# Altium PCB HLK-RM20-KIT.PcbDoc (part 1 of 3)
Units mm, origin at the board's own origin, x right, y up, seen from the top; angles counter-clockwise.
Board outline 152 x 109 mm, 2 copper layers (Top Layer, Bottom Layer), stack 0.325 mm thick; 212 components, 285 nets, 988 pads, 747 vias.
Unrouted connection lines stored in the file: 195.
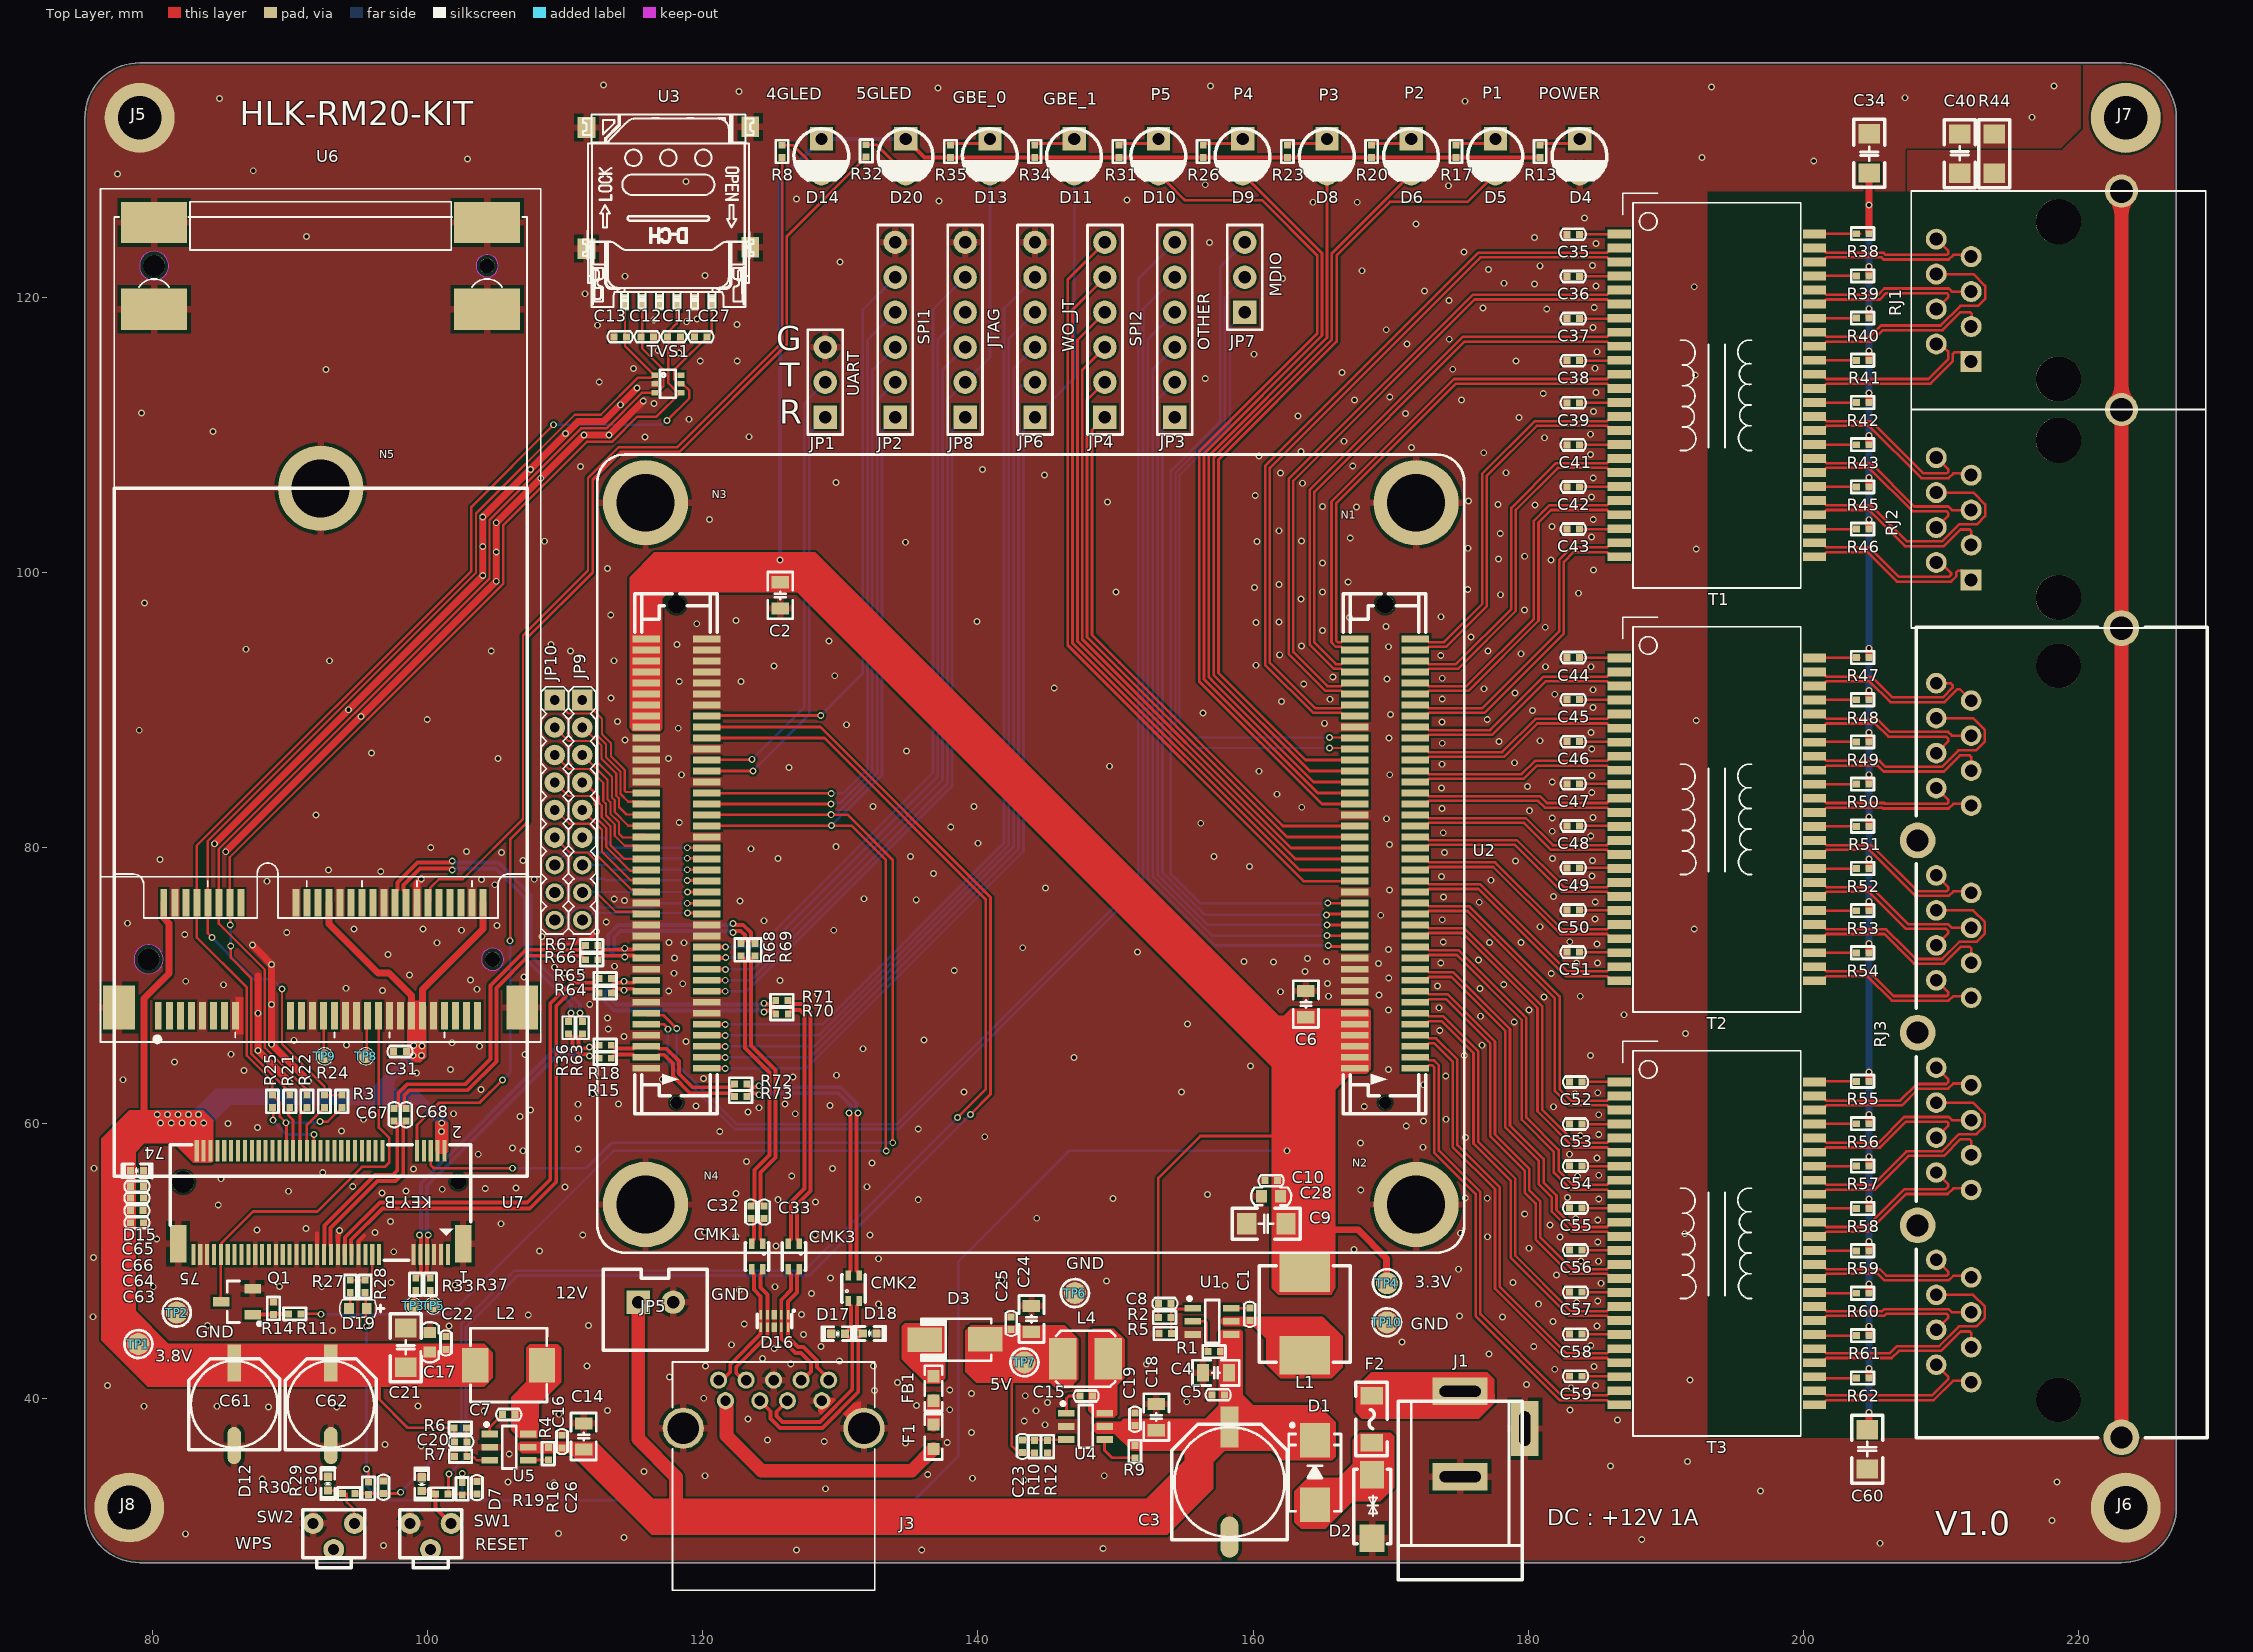
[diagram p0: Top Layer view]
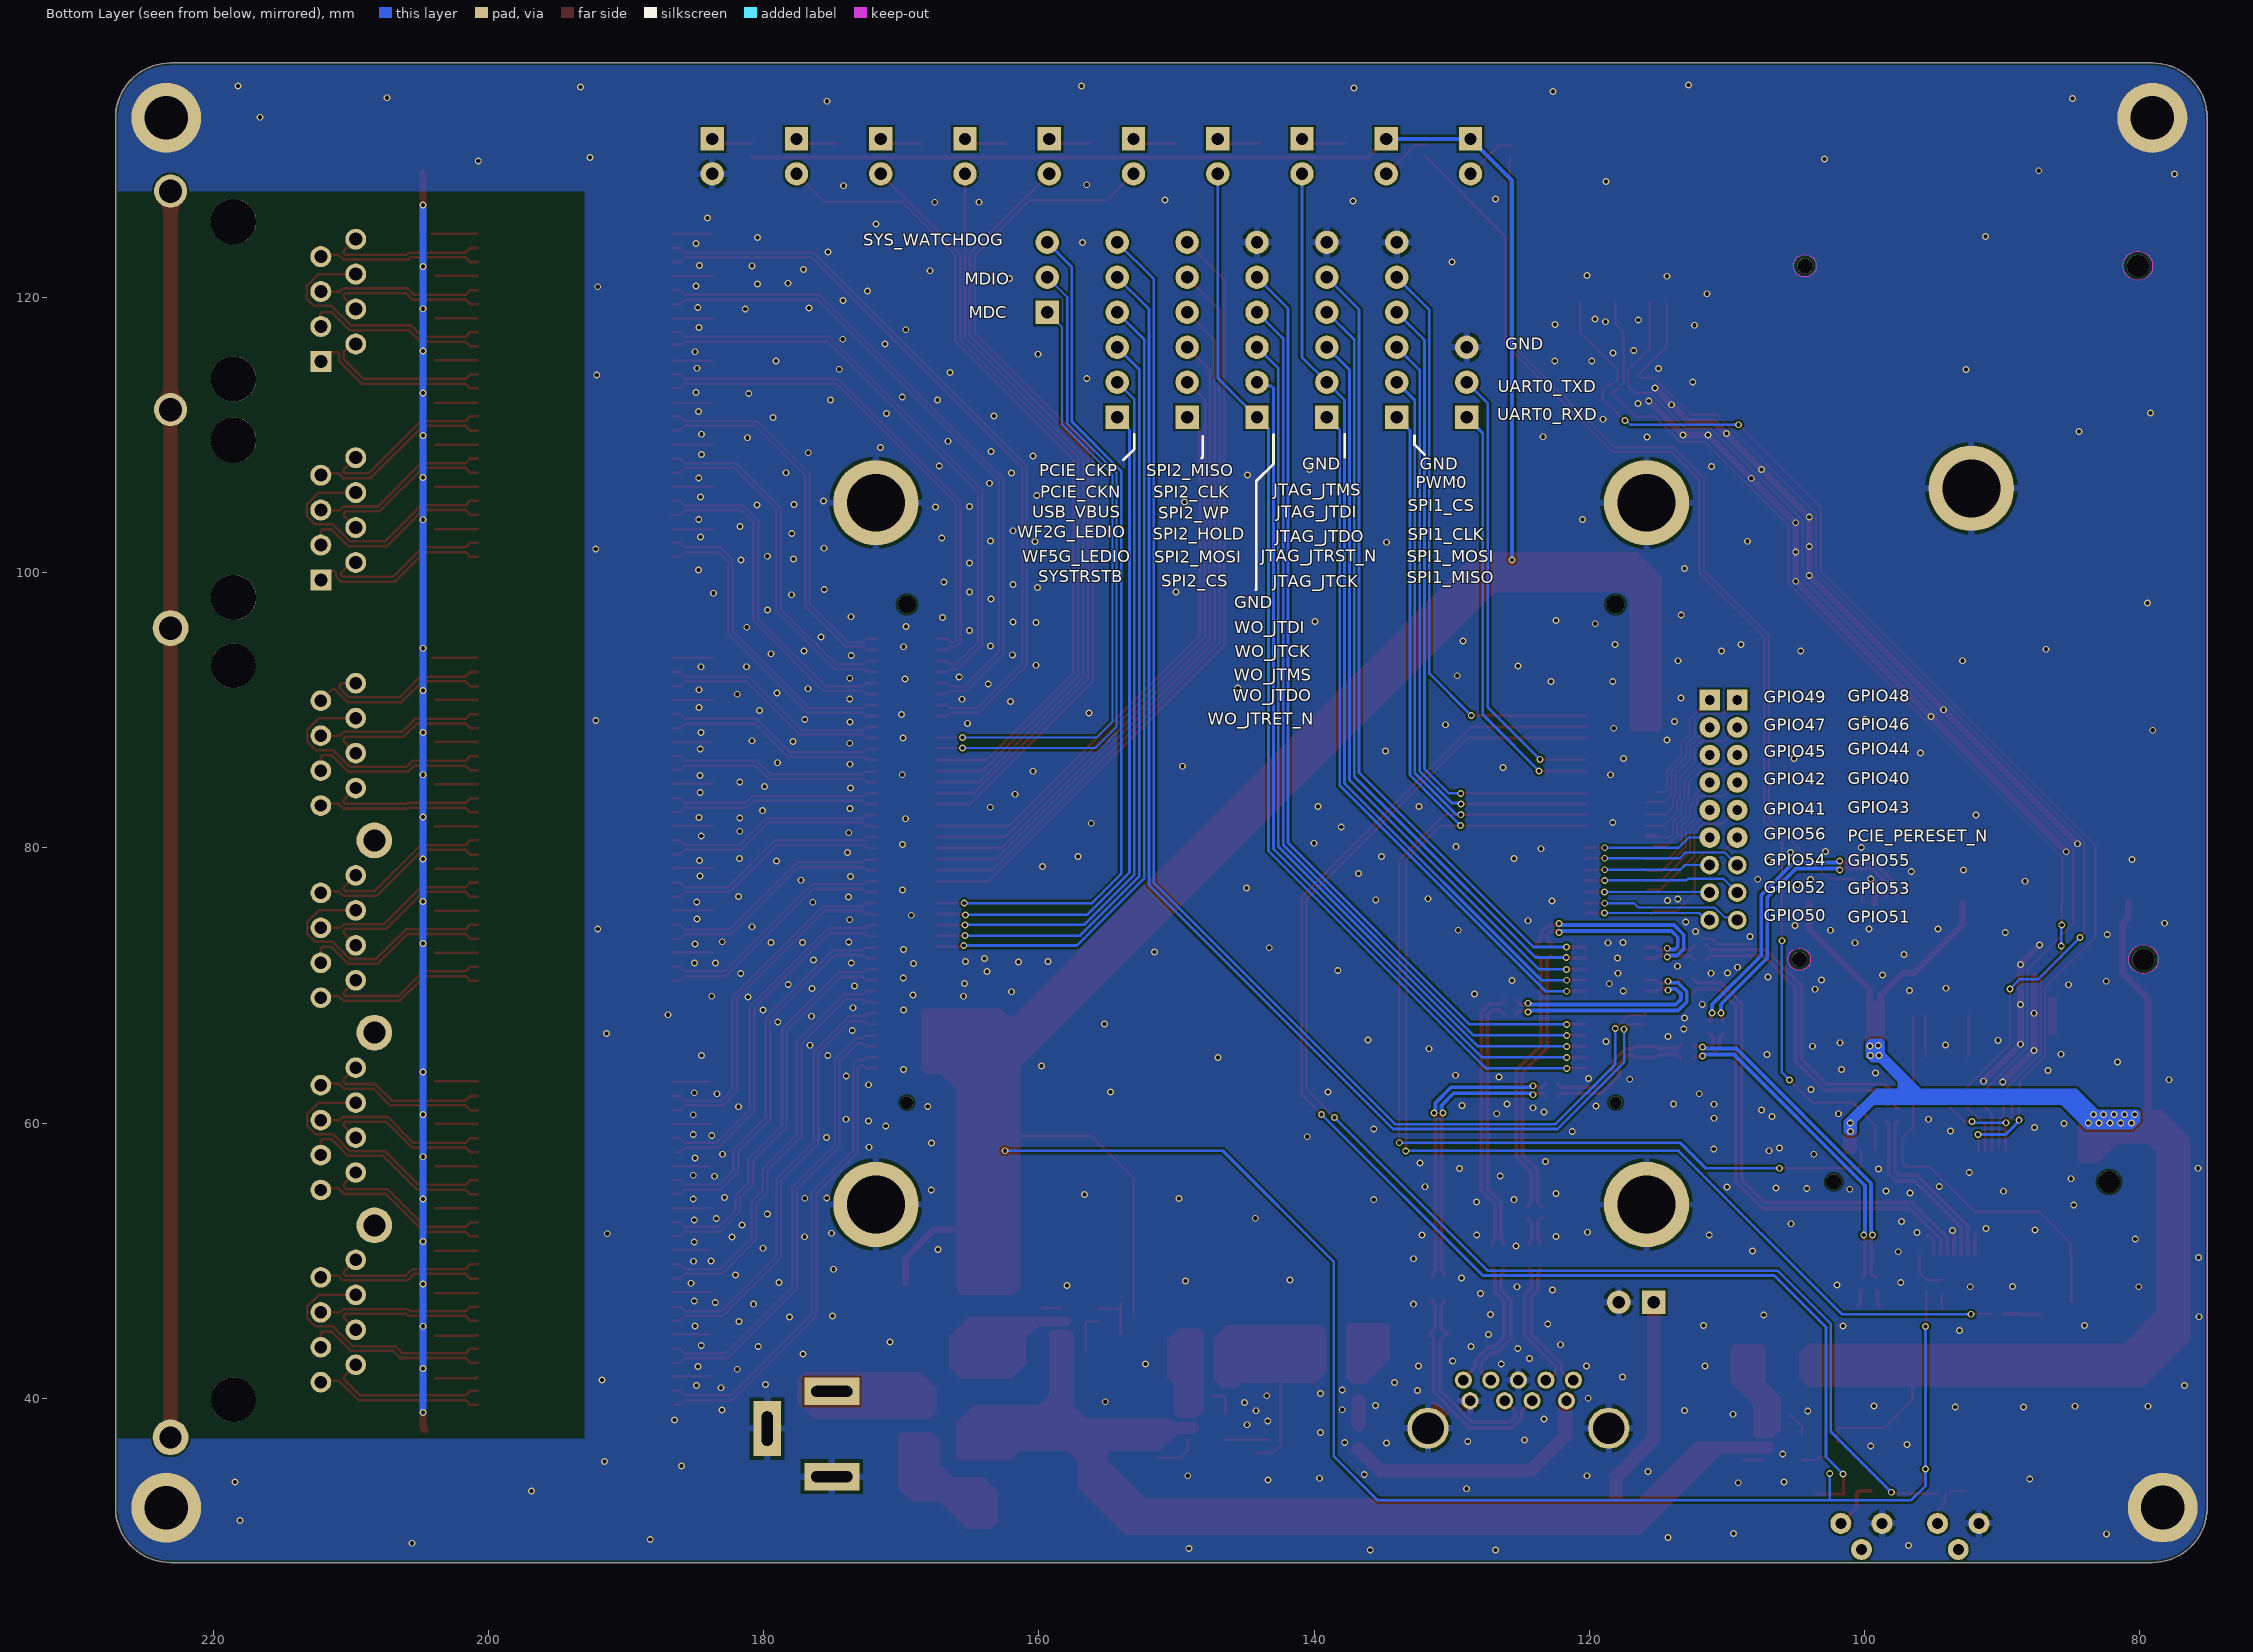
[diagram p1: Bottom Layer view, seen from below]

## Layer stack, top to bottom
Top Solder: solder mask 0.0102, Solder Resist, Dk 3.5
Top Layer: signal copper 0.0356
Dielectric1: core 0.254, FR-4, Dk 4.2
Bottom Layer: signal copper 0.0356
Bottom Solder: solder mask 0.0102, Solder Resist, Dk 3.5

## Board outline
75.089,32.059 75.089,133.053 cw(c79.089,133.053) 79.089,137.053 223.092,137.053 223.092,137.048 cw(c223.092,133.048) 227.092,133.048 227.093,133.047 227.093,32.053 cw(c223.093,32.053) 223.093,28.053 79.095,28.053 79.09,28.058 cw(c79.09,32.058)

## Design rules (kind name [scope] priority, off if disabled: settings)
Clearance [All] p1: gap=0.152 ignorepadtopadclearanceinfootprint=FALSE
DiffPairsRouting 90OHM [InNetClass('90OHM')] p1: maxlimit=0.152 minlimit=0.152 mostfreqgap=0.152 toplayer_minwidth=0.283 toplayer_maxwidth=0.283 toplayer_prefwidth=0.283 bottomlayer_minwidth=0.283 bottomlayer_maxwidth=0.283 bottomlayer_prefwidth=0.283 maxuncoupledlength=12.7
DiffPairsRouting 100OHM [InNetClass('100OHM')] p2: maxlimit=0.152 minlimit=0.152 mostfreqgap=0.152 toplayer_minwidth=0.188 toplayer_maxwidth=0.188 toplayer_prefwidth=0.188 bottomlayer_minwidth=0.188 bottomlayer_maxwidth=0.188 bottomlayer_prefwidth=0.188 maxuncoupledlength=12.7
FabricationTestPointUsage TestPointUsage [All] p1: valid=0 allowmultiple=FALSE
FabricationTestpoint Testpoint [All] p1: side=3 testpointundercomponent=TRUE minsize=1.016 maxsize=2.54 preferedsize=1.524 minholesize=0 maxholesize=1.016 preferedholesize=0.813 testpointgrid=0.025 allowsidetop=TRUE allowsidebottom=TRUE usegrid=TRUE gridtolerance=0
HoleSize [All] p1: absolutevalues=TRUE maxlimit=5 minlimit=0.2 maxpercent=80.000 minpercent=20.000
MatchedLengths DiffPair_USB2.0_5GMatchedLengths [InDifferentialPair ('USB_5G')] p1: tolerance=10 checknetsindiffpair=TRUE checkdiffpairvsdiffpair=FALSE checkxsignals=FALSE checkothers=FALSE
MatchedLengths DiffPair_USB2.0_7621MatchedLengths [InDifferentialPair ('USB')] p2: tolerance=10 checknetsindiffpair=TRUE checkdiffpairvsdiffpair=FALSE checkxsignals=FALSE checkothers=FALSE
MatchedLengths DiffPair_USB3.0TXMatchedLengths [InDifferentialPair ('SSUSB_TX')] p3: tolerance=0.7 checknetsindiffpair=TRUE checkdiffpairvsdiffpair=FALSE checkxsignals=FALSE checkothers=FALSE
MatchedLengths DiffPair_USB3.0RXMatchedLengths [InDifferentialPair ('SSUSB_RX')] p4: tolerance=0.7 checknetsindiffpair=TRUE checkdiffpairvsdiffpair=FALSE checkxsignals=FALSE checkothers=FALSE
MatchedLengths DiffPair_USB2.0_7621MatchedLengths_1 [InDifferentialPair ('USB')] p5: tolerance=5 checknetsindiffpair=TRUE checkdiffpairvsdiffpair=FALSE checkxsignals=FALSE checkothers=FALSE
MatchedLengths DiffPair_USB2.0_5GMatchedLengths_1 [InDifferentialPair ('USB_5G')] p6: tolerance=1 checknetsindiffpair=TRUE checkdiffpairvsdiffpair=FALSE checkxsignals=FALSE checkothers=FALSE
MatchedLengths DiffPair_USB3.0TXMatchedLengths_1 [InDifferentialPair ('SSUSB_TX')] p7: tolerance=0.7 checknetsindiffpair=TRUE checkdiffpairvsdiffpair=FALSE checkxsignals=FALSE checkothers=FALSE
MatchedLengths DiffPair_USB3.0RXMatchedLengths_1 [InDifferentialPair ('SSUSB_RX')] p8: tolerance=0.7 checknetsindiffpair=TRUE checkdiffpairvsdiffpair=FALSE checkxsignals=FALSE checkothers=FALSE
MatchedLengths DiffPair_PCIE_TXMatchedLengths [InDifferentialPair ('PCIE_TX')] p9: tolerance=0.7 checknetsindiffpair=TRUE checkdiffpairvsdiffpair=FALSE checkxsignals=FALSE checkothers=FALSE
MatchedLengths DiffPair_PCIE_CLKMatchedLengths [InDifferentialPair ('PCIE_CLK')] p10: tolerance=0.7 checknetsindiffpair=TRUE checkdiffpairvsdiffpair=FALSE checkxsignals=FALSE checkothers=FALSE
MatchedLengths DiffPair_PCIE_RXMatchedLengths [InDifferentialPair ('PCIE_RX')] p11: tolerance=0.7 checknetsindiffpair=TRUE checkdiffpairvsdiffpair=FALSE checkxsignals=FALSE checkothers=FALSE
MatchedLengths DiffPair_PCIE_RXMatchedLengths_1 [InDifferentialPair ('PCIE_RX')] p12: tolerance=25.4 checknetsindiffpair=TRUE checkdiffpairvsdiffpair=FALSE checkxsignals=FALSE checkothers=FALSE
MatchedLengths [InDifferentialPair ('PCIE_TX')] p13: tolerance=25.4 checknetsindiffpair=TRUE checkdiffpairvsdiffpair=FALSE checkxsignals=FALSE checkothers=FALSE
MatchedLengths DiffPair_PCIE_TXMatchedLengths_1 [InDifferentialPair ('PCIE_TX')] p14: tolerance=0.7 checknetsindiffpair=TRUE checkdiffpairvsdiffpair=FALSE checkxsignals=FALSE checkothers=FALSE
MatchedLengths DiffPair_1MatchedLengths [InDifferentialPair ('PCIE_TX')] p15: tolerance=0.7 checknetsindiffpair=TRUE checkdiffpairvsdiffpair=FALSE checkxsignals=FALSE checkothers=FALSE
PolygonConnect 部分焊盘十字 [All vs HasPad ('U7-76') Or HasPad ('U7-77')Or HasPad ('j4-1')Or HasPad ('j4-2')Or HasPad ('j4-3')Or HasPad ('j4-4')  Or HasPad ('U7-0')        Or HasPad ('U3-0') Or HasPad ('U6-55')Or HasPad ('U6-56') Or HasPad ('U6-63') Or HasPad ('U6-64') Or HasPad ('U6-65') Or HasPad ('U6-66')  Or HasPad ('U2-0')] p1: connectstyle=Relief reliefconductorwidth=0.5 reliefentries=4 polygonreliefangle="90 Angle" airgapwidth=0.254
PolygonConnect M3 [All vs HasFootprint('M3 125X200')] p2: connectstyle=Direct reliefconductorwidth=0.254 reliefentries=4 polygonreliefangle="90 Angle" airgapwidth=0.254
PolygonConnect 全连 [InComponent('D16') or  InComponent('u6')or  InComponent('u1') or  InComponent('u2')  or  InComponent('u3') or  InComponent('u4')or  InComponent('tvs1')          or  InComponent('u7')] p3: connectstyle=Direct reliefconductorwidth=0.254 reliefentries=4 polygonreliefangle="90 Angle" airgapwidth=0.254
PolygonConnect 焊盘全连通孔十字 [(HasFootprint('NANO-SIM_SMN-327') OR HasFootprint('HLK-RM20') OR HasFootprint('C 1206_L') OR HasFootprint('R 1206_L')OR HasFootprint('TEST 1.6')  )] p4: thpad.connectstyle=Relief thpad.reliefconductorwidth=0.5 thpad.reliefentries=4 thpad.polygonreliefangle="90 Angle" thpad.airgapwidth=0.254 smdpad.connectstyle=Direct smdpad.reliefconductorwidth=0.254 smdpad.reliefentries=4 smdpad.polygonreliefangle="90 Angle" smdpad.airgapwidth=0.254 via.connectstyle=Direct via.reliefconductorwidth=0.254 via.reliefentries=4 via.polygonreliefangle="90 Angle" via.airgapwidth=0.254
PolygonConnect [All] p5: thpad.connectstyle=Relief thpad.reliefconductorwidth=0.5 thpad.reliefentries=4 thpad.polygonreliefangle="90 Angle" thpad.airgapwidth=0.254 smdpad.connectstyle=Relief smdpad.reliefconductorwidth=0.5 smdpad.reliefentries=4 smdpad.polygonreliefangle="90 Angle" smdpad.airgapwidth=0.254 via.connectstyle=Direct via.reliefconductorwidth=0.254 via.reliefentries=4 via.polygonreliefangle="90 Angle" via.airgapwidth=0.254
RoutingVias [All] p1: holewidth=0.4 width=0.4 viastyle="Through Hole" minholewidth=0.2 minwidth=0.4 maxholewidth=0.6 maxwidth=0.8
SilkToSilkClearance [All] p1: silktosilkclearance=0
SolderMaskExpansion [All] p1: expansion=0.102 istentingtop=FALSE
Width Width_90ohm [InNetClass('90ohm')] p1 off: maxlimit=0.283 minlimit=0.283 preferedwidth=0.283 minimp=50.000000 maximp=50.000000 favimp=50.000000
Width Width_100ohm [InNetClass('100ohm')] p2 off: maxlimit=0.188 minlimit=0.188 preferedwidth=0.188
Width [All] p3: maxlimit=5 minlimit=0.152 preferedwidth=0.152
25 further rules are at their usual default settings.

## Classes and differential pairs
component class HLK-RM20-KIT-5G: C61 C62 C63 C64 C65 C66 C67 C68 D15 D19 D20 R21 R22 R24 R25 R27 R28 R32 R33 R37 R64 R65 R66 R67 TP3 TP5 U7
component class HLK-RM20-KIT-4G: 1 2 C7 C11 C12 C13 C14 C16 C17 C20 C21 C22 C27 C31 D14 L2 Q1 R3 R4 R6 R7 R8 R11 R14 R15 R18 R36 R63 TP1 TP2 TP8 TP9 TVS1 U3 U5 U6
net class 90OHM: 4GUSB_D1_N 4GUSB_D1_P 4GUSB_D_N 4GUSB_D_P 5G_SSUSB_RX_N 5G_SSUSB_RX_P 5G_USB_TX_N 5G_USB_TX_P DZSS_RX_N DZSS_RX_P DZSS_TX_N DZSS_TX_P DZUSB_D_N DZUSB_D_P NetCMK1_3 NetCMK1_4 NetCMK2_1 NetCMK2_2 NetCMK3_3 NetCMK3_4 SS_RX_N SS_RX_P SS_TX_N SS_TX_P USB_D_N USB_D_P
net class 100OHM: ESW_A_P1_TXV_N ESW_A_P1_TXV_P ESW_A_P2_TXV_N ESW_A_P2_TXV_P ESW_A_P3_TXV_N ESW_A_P3_TXV_P ESW_A_P4_TXV_N ESW_A_P4_TXV_P ESW_A_P5_TXV_N ESW_A_P5_TXV_P ESW_B_P1_TXV_N ESW_B_P1_TXV_P ESW_B_P2_TXV_N ESW_B_P2_TXV_P ESW_B_P3_TXV_N ESW_B_P3_TXV_P ESW_B_P4_TXV_N ESW_B_P4_TXV_P ESW_B_P5_TXV_N ESW_B_P5_TXV_P ESW_C_P1_TXV_N ESW_C_P1_TXV_P ESW_C_P2_TXV_N ESW_C_P2_TXV_P ESW_C_P3_TXV_N ESW_C_P3_TXV_P ESW_C_P4_TXV_N ESW_C_P4_TXV_P ESW_C_P5_TXV_N ESW_C_P5_TXV_P ESW_D_P1_TXV_N ESW_D_P1_TXV_P ESW_D_P2_TXV_N ESW_D_P2_TXV_P ESW_D_P3_TXV_N ESW_D_P3_TXV_P ESW_D_P4_TXV_N ESW_D_P4_TXV_P ESW_D_P5_TXV_N ESW_D_P5_TXV_P MTXV_P0_A_N MTXV_P0_A_P MTXV_P0_B_N MTXV_P0_B_P MTXV_P0_C_N MTXV_P0_C_P MTXV_P0_D_N MTXV_P0_D_P MTXV_P1_A_N MTXV_P1_A_P MTXV_P1_B_N MTXV_P1_B_P MTXV_P1_C_N MTXV_P1_C_P MTXV_P1_D_N MTXV_P1_D_P MTXV_P2_A_N MTXV_P2_A_P MTXV_P2_B_N MTXV_P2_B_P MTXV_P2_C_N MTXV_P2_C_P MTXV_P2_D_N MTXV_P2_D_P MTXV_P3_A_N MTXV_P3_A_P MTXV_P3_B_N MTXV_P3_B_P MTXV_P3_C_N MTXV_P3_C_P MTXV_P3_D_N MTXV_P3_D_P MTXV_P4_A_N MTXV_P4_A_P MTXV_P4_B_N MTXV_P4_B_P MTXV_P4_C_N MTXV_P4_C_P MTXV_P4_D_N MTXV_P4_D_P MTXV_P5_A_N MTXV_P5_A_P MTXV_P5_B_N MTXV_P5_B_P MTXV_P5_C_N MTXV_P5_C_P MTXV_P5_D_N MTXV_P5_D_P P0_A_TXV_N P0_A_TXV_P P0_B_TXV_N P0_B_TXV_P P0_C_TXV_N P0_C_TXV_P P0_D_TXV_N P0_D_TXV_P
component class HLK-RM20-KIT-POWER_LED: 56 C1 C2 C3 C4 C5 C6 C8 C9 C10 C15 C18 C19 C23 C24 C25 C26 C28 C30 C32 C33 CMK1 CMK2 CMK3 D1 D2 D3 D4 D5 D6 D7 D8 D9 D10 D11 D12 D13 D16 D17 D18 F1 F2 FB1 J1 J3 J5 J6 J7 J8 JP1 JP2 JP3 JP4 JP5 JP6 JP7 JP8 JP9 JP10 L1 L4 m R1 R2 R5 R9 R10 R12 R13 R16 R17 R19 R20 R23 R26 R29 R30 R31 R34 R35 R68 R69 R70 R71 R72 R73 SW1 SW2 TP4 TP6 TP7 TP10 U1 U2 U4
component class HLK-RM20-KIT-RJ45: C34 C35 C36 C37 C38 C39 C40 C41 C42 C43 C44 C45 C46 C47 C48 C49 C50 C51 C52 C53 C54 C55 C56 C57 C58 C59 C60 R38 R39 R40 R41 R42 R43 R44 R45 R46 R47 R48 R49 R50 R51 R52 R53 R54 R55 R56 R57 R58 R59 R60 R61 R62 RJ1 RJ2 RJ3 T1 T2 T3
differential pair 4GUSB_D1: +4GUSB_D1_P -4GUSB_D1_N
differential pair USB_D: +USB_D_P -USB_D_N
differential pair DZUSB_D: +DZUSB_D_P -DZUSB_D_N
differential pair DZSS_TX: +DZSS_TX_P -DZSS_TX_N
differential pair DZSS_RX: +DZSS_RX_P -DZSS_RX_N
differential pair 4GUSB_D: +4GUSB_D_P -4GUSB_D_N
differential pair 5G_USB_TX: +5G_USB_TX_P -5G_USB_TX_N
differential pair 5G_SSUSB_TX: +5G_SSUSB_TX_P -5G_SSUSB_TX_N
differential pair 5G_SSUSB_RX: +5G_SSUSB_RX_P -5G_SSUSB_RX_N
differential pair MTXV_P5_D: +MTXV_P5_D_P -MTXV_P5_D_N
differential pair MTXV_P5_C: +MTXV_P5_C_P -MTXV_P5_C_N
differential pair MTXV_P5_B: +MTXV_P5_B_P -MTXV_P5_B_N
differential pair MTXV_P5_A: +MTXV_P5_A_P -MTXV_P5_A_N
differential pair MTXV_P4_D: +MTXV_P4_D_P -MTXV_P4_D_N
differential pair MTXV_P4_C: +MTXV_P4_C_P -MTXV_P4_C_N
differential pair MTXV_P4_B: +MTXV_P4_B_P -MTXV_P4_B_N
differential pair MTXV_P4_A: +MTXV_P4_A_P -MTXV_P4_A_N
differential pair MTXV_P3_D: +MTXV_P3_D_P -MTXV_P3_D_N
differential pair MTXV_P3_C: +MTXV_P3_C_P -MTXV_P3_C_N
differential pair MTXV_P3_B: +MTXV_P3_B_P -MTXV_P3_B_N
differential pair MTXV_P3_A: +MTXV_P3_A_P -MTXV_P3_A_N
differential pair MTXV_P2_D: +MTXV_P2_D_P -MTXV_P2_D_N
differential pair MTXV_P2_C: +MTXV_P2_C_P -MTXV_P2_C_N
differential pair MTXV_P2_B: +MTXV_P2_B_P -MTXV_P2_B_N
differential pair MTXV_P2_A: +MTXV_P2_A_P -MTXV_P2_A_N
differential pair MTXV_P1_D: +MTXV_P1_D_P -MTXV_P1_D_N
differential pair MTXV_P1_C: +MTXV_P1_C_P -MTXV_P1_C_N
differential pair MTXV_P1_B: +MTXV_P1_B_P -MTXV_P1_B_N
differential pair MTXV_P1_A: +MTXV_P1_A_P -MTXV_P1_A_N
differential pair MTXV_P0_D: +MTXV_P0_D_P -MTXV_P0_D_N
differential pair MTXV_P0_C: +MTXV_P0_C_P -MTXV_P0_C_N
differential pair MTXV_P0_B: +MTXV_P0_B_P -MTXV_P0_B_N
differential pair MTXV_P0_A: +MTXV_P0_A_P -MTXV_P0_A_N
differential pair P0_D_TXV: +P0_D_TXV_P -P0_D_TXV_N
differential pair P0_C_TXV: +P0_C_TXV_P -P0_C_TXV_N
differential pair P0_B_TXV: +P0_B_TXV_P -P0_B_TXV_N
differential pair P0_A_TXV: +P0_A_TXV_P -P0_A_TXV_N
differential pair ESW_D_P5_TXV: +ESW_D_P5_TXV_P -ESW_D_P5_TXV_N
differential pair ESW_D_P4_TXV: +ESW_D_P4_TXV_P -ESW_D_P4_TXV_N
differential pair ESW_D_P3_TXV: +ESW_D_P3_TXV_P -ESW_D_P3_TXV_N
differential pair ESW_D_P2_TXV: +ESW_D_P2_TXV_P -ESW_D_P2_TXV_N
differential pair ESW_D_P1_TXV: +ESW_D_P1_TXV_P -ESW_D_P1_TXV_N
differential pair ESW_C_P5_TXV: +ESW_C_P5_TXV_P -ESW_C_P5_TXV_N
differential pair ESW_C_P4_TXV: +ESW_C_P4_TXV_P -ESW_C_P4_TXV_N
differential pair ESW_C_P3_TXV: +ESW_C_P3_TXV_P -ESW_C_P3_TXV_N
differential pair ESW_C_P2_TXV: +ESW_C_P2_TXV_P -ESW_C_P2_TXV_N
differential pair ESW_C_P1_TXV: +ESW_C_P1_TXV_P -ESW_C_P1_TXV_N
differential pair ESW_B_P5_TXV: +ESW_B_P5_TXV_P -ESW_B_P5_TXV_N
differential pair ESW_B_P4_TXV: +ESW_B_P4_TXV_P -ESW_B_P4_TXV_N
differential pair ESW_B_P3_TXV: +ESW_B_P3_TXV_P -ESW_B_P3_TXV_N
differential pair ESW_B_P2_TXV: +ESW_B_P2_TXV_P -ESW_B_P2_TXV_N
differential pair ESW_B_P1_TXV: +ESW_B_P1_TXV_P -ESW_B_P1_TXV_N
differential pair ESW_A_P5_TXV: +ESW_A_P5_TXV_P -ESW_A_P5_TXV_N
differential pair ESW_A_P4_TXV: +ESW_A_P4_TXV_P -ESW_A_P4_TXV_N
differential pair ESW_A_P3_TXV: +ESW_A_P3_TXV_P -ESW_A_P3_TXV_N
differential pair ESW_A_P2_TXV: +ESW_A_P2_TXV_P -ESW_A_P2_TXV_N
differential pair ESW_A_P1_TXV: +ESW_A_P1_TXV_P -ESW_A_P1_TXV_N
differential pair SS_TX: +SS_TX_P -SS_TX_N
differential pair SS_RX: +SS_RX_P -SS_RX_N

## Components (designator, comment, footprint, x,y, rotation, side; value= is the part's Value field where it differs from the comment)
C1 "100nF" "C 0402_L" 159.751,46.1 r270 top
C2 "22uF" "C 0805_L" 125.628,98.349 r90 top value=100pF
C3 "220uF" "CT 8*12 - C" 158.283,33.908 r90 top
C4 "10uF" "C 0805_L" 157.293,41.85 r0 top value=100pF
C5 "100nF" "C 0402_L" 157.457,40.25 r180 top
C6 "22uF" "C 0805_L" 163.83,68.646 r270 top value=100pF
C7 "100nF" "C 0402_L" 105.9,38.816 r0 top
C8 "100pF" "C 0402_L" 153.586,46.888 r180 top
C9 "47uF" "C 1206_L" 160.937,52.69 r0 top
C10 "100nF" "C 0402_L" 161.306,55.813 r180 top
C11 "33pF" "C 0402_L" 117.909,117.145 r0 top
C12 "33pF" "C 0402_L" 115.952,117.145 r0 top
C13 "33pF" "C 0402_L" 113.995,117.145 r180 top
C14 "10uF" "C 0805_L" 111.341,37.221 r270 top value=100pF
C15 "100nF" "C 0402_L" 147.857,40.17 r0 top
C16 "100nF" "C 0402_L" 109.766,36.855 r90 top
C17 "10uF" "C 0603_L" 100.165,44.08 r90 top
C18 "10uF" "C 0805_L" 152.956,38.63 r270 top value=100pF
C19 "100nF" "C 0402_L" 151.403,38.474 r90 top
C20 "100pF" "C 0402_L" 102.415,36.836 r180 top
C21 "47uF" "C 1206_l" 98.412,43.71 r270 top
C22 "100nF" "C 0402_L" 101.333,44.018 r90 top
C23 "47pF" "C 0402_L" 143.23,36.504 r270 top value=100pF
C24 "22uF" "C 0805_L" 143.884,45.761 r270 top value=100pF
C25 "100nF" "C 0402_L" 142.411,45.441 r90 top
C26 "100nF" "C 0402_L" 103.582,33.503 r270 top
C27 "100nF" "C 0402_L" 119.865,117.145 r0 top
C28 "10uF" "C 0603_L" 161.301,54.675 r180 top
C30 "100nF" "C 0402_L" 96.794,33.534 r270 top
C31 "100nF" "C 0402_L" 97.994,65.199 r180 top
C32 "0.1uF" "C 0402_L" 123.501,53.529 r90 top
C33 "0.1uF" "C 0402_L" 124.458,53.529 r90 top
C34 "1000pF,2KV,SMD,1206" "C 1206_L" 204.772,130.444 r90 top
C35 "0.1uF" "C 0402_L" 183.259,124.588 r0 top
C36 "0.1uF" "C 0402_L" 183.259,121.528 r0 top
C37 "0.1uF" "C 0402_L" 183.259,118.468 r0 top
C38 "0.1uF" "C 0402_L" 183.259,115.408 r0 top
C39 "0.1uF" "C 0402_L" 183.259,112.348 r0 top
C40 "1000pF/2KV" "C 1206_L" 211.34,130.478 r270 top
C41 "0.1uF" "C 0402_L" 183.259,109.288 r0 top
C42 "0.1uF" "C 0402_L" 183.259,106.229 r0 top
C43 "0.1uF" "C 0402_L" 183.259,103.169 r0 top
C44 "0.1uF" "C 0402_L" 183.259,93.831 r0 top
C45 "0.1uF" "C 0402_L" 183.259,90.773 r0 top
C46 "0.1uF" "C 0402_L" 183.259,87.715 r0 top
C47 "0.1uF" "C 0402_L" 183.259,84.656 r0 top
C48 "0.1uF" "C 0402_L" 183.259,81.598 r0 top
C49 "0.1uF" "C 0402_L" 183.259,78.54 r0 top
C50 "0.1uF" "C 0402_L" 183.259,75.481 r0 top
C51 "0.1uF" "C 0402_L" 183.259,72.423 r0 top
C52 "0.1uF" "C 0402_L" 183.428,62.987 r0 top
C53 "0.1uF" "C 0402_L" 183.428,59.931 r0 top
C54 "0.1uF" "C 0402_L" 183.428,56.876 r0 top
C55 "0.1uF" "C 0402_L" 183.428,53.821 r0 top
C56 "0.1uF" "C 0402_L" 183.428,50.766 r0 top
C57 "0.1uF" "C 0402_L" 183.428,47.711 r0 top
C58 "0.1uF" "C 0402_L" 183.428,44.656 r0 top
C59 "0.1uF" "C 0402_L" 183.428,41.601 r0 top
C60 "1000pF,2KV,SMD,1206" "C 1206_L" 204.62,36.312 r270 top
C61 "220uF" "CT 6*6 - R" 85.941,39.562 r90 top
C62 "220uF" "CT 6*6 - R" 92.97,39.562 r90 top
C63 "1uF" "C 0402_L" 78.879,52.756 r0 top
C64 "100nF" "C 0402_L" 78.874,53.631 r0 top
C65 "33pF" "C 0402_L" 78.879,55.397 r0 top
C66 "10pF" "C 0402_L" 78.879,54.559 r0 top
C67 "0.1uF" "C 0402_L" 97.574,60.604 r270 top
C68 "0.1uF" "C 0402_L" 98.447,60.607 r270 top
CMK1 "ACM2012E-2P" SMD_4P 123.941,50.303 r270 top
CMK2 "ACM2012E-2P" SMD_4P 130.962,47.992 r90 top
CMK3 "ACM2012E-2P" SMD_4P 126.619,50.303 r270 top
D1 "SS34" SMB 164.487,34.598 r90 top
D2 "SMAJ26CA" DO-214AC 168.641,29.827 r90 top
D3 "SS12" SMA 138.322,44.272 r180 top
D4 "RED" "LED 3MM-R" 183.729,130.251 r270 top
D5 "YELLOW" "LED 3MM-Y" 177.606,130.251 r270 top
D6 "YELLOW" "LED 3MM-Y" 171.484,130.251 r270 top
D7 "BPESD0402-05ST" esd0402 99.569,33.759 r270 top
D8 "YELLOW" "LED 3MM-Y" 165.361,130.251 r270 top
D9 "YELLOW" "LED 3MM-Y" 159.238,130.251 r270 top
D10 "YELLOW" "LED 3MM-Y" 153.116,130.251 r270 top
D11 "YELLOW" "LED 3MM-Y" 146.993,130.251 r270 top
D12 "BPESD0402-05ST" esd0402 92.755,33.789 r270 top
D13 "YELLOW" "LED 3MM-Y" 140.871,130.251 r270 top
D14 "RED" "LED 3MM-G" 128.626,130.251 r270 top
D15 "ESDA-05N" ESD0402#1 78.888,57.54 r180 top
D16 "B0524P" DFN-10 125.203,45.613 r180 top
D17 "BPESD0402-05ST" ESD0402#2 129.826,44.695 r0 top
D18 "BPESD0402-05ST" ESD0402#2 132.119,44.709 r180 top
D19 "RED" "LED 0603B-L" 94.932,46.507 r180 top
D20 "G" "LED 3MM-G" 134.748,130.251 r270 top
F1 "1A" "FU 0603" 136.772,37.211 r90 top
F2 "2A" "FU 1206" 168.607,38.485 r270 top
FB1 "CBM160808U101T" "L 0603" 136.772,40.716 r270 top
J1 "DC-044B" DC-005 175.038,34.299 r270 top
J3 "USB3.0" USB3.0-9P-DIP 125.148,39.57 r0 top locked
J5 "M3" "M3 125X200" 79.077,133.055 r90 top
J6 "M3" "M3 125X200" 223.413,32.053 r90 top
J7 "M3" "M3 125X200" 223.413,133.053 r90 top
J8 "M3" "M3 125X200" 78.315,32.058 r90 top
JP1 "HDR-1X3" HDR2.54-LI-3P 128.905,113.843 r90 top
JP2 "HDR-1X6" HDR2.54-LI-6P 133.985,117.653 r90 top
JP3 "HDR-1X6" HDR2.54-LI-6P 154.305,117.653 r90 top
JP4 "HDR-1X6" HDR2.54-LI-6P 149.225,117.653 r90 top
JP5 "HDR-1X2" XH2.54-LI-2P 116.586,46.99 r0 top
JP6 "HDR-1X6" HDR2.54-LI-6P 144.145,117.653 r90 top
JP7 "HDR-1X3" HDR2.54-LI-3P 159.385,121.463 r90 top
JP8 "HDR-1X6" HDR2.54-LI-6P 139.065,117.653 r90 top
JP9 "HDR-1X9" HDR2.0-LI-9P 111.241,90.75 r270 top
JP10 "HDR-1X9" HDR2.0-LI-9P 109.241,90.75 r270 top
L1 "4.7uH" "L 6*6" 163.749,46.123 r90 top
L2 "4.7uH" "L 5*5" 105.892,42.404 r0 top
L4 "4.7uH" "L 4*4" 147.821,42.875 r180 top
Q1 "SS8050" SOT23-3N 86.134,47.017 r90 top
R1 "47K" "R 0402_L" 157.179,43.393 r180 top
R2 "100K/1%" "R 0402_L" 153.535,45.872 r0 top
R3 "10K" "R 0402_L" 93.764,61.603 r270 top
R4 "47K" "R 0402_L" 108.771,35.998 r270 top
R5 "22.1K/1%" "R 0402_L" 153.618,44.71 r180 top
R6 "53.6K/1%" "R 0402_L" 102.349,37.846 r0 top
R7 "10K/1%" "R 0402_L" 102.415,35.785 r180 top
R8 "Res1" "R 0402_L" 125.755,130.632 r270 top value=1k
R9 "47K" "R 0402_L" 151.403,36.149 r270 top
R10 "73.2K/1%" "R 0402_L" 144.123,36.457 r90 top
R11 "1K" "R 0402_L" 90.319,46.13 r0 top
R12 "10K/1%" "R 0402_L" 145.048,36.506 r270 top
R13 "1K" "R 0402_L" 180.848,130.632 r270 top
R14 "47K" "R 0402_L" 88.804,46.556 r270 top
R15 "0R" "R 0402_L" 112.878,64.707 r0 top
R16 "10K" "R 0402_l" 102.511,33.439 r270 top
R17 "1K" "R 0402_L" 174.727,130.632 r270 top
R18 "0R" "R 0402_L" 112.878,65.656 r0 top
R19 "1K" "R 0402_l" 101.017,33.039 r0 top
R20 "1K" "R 0402_L" 168.605,130.632 r270 top
R21 "22R" "R 0402_L" 89.978,61.603 r270 top
R22 "22R" "R 0402_L" 91.24,61.603 r270 top
R23 "1K" "R 0402_L" 162.484,130.632 r270 top
R24 "22R" "R 0402_L" 92.502,61.603 r270 top
R25 "47K" "R 0402_L" 88.717,61.603 r270 top
R26 "1K" "R 0402_L" 156.363,130.632 r270 top
R27 "1K" "R 0402_L" 94.386,48.104 r90 top value=1k
R28 "10K" "R 0402_L" 95.458,48.158 r270 top
R29 "10K" "R 0402_l" 95.702,33.47 r270 top
R30 "1K" "R 0402_l" 94.256,33.07 r0 top
R31 "1K" "R 0402_L" 150.241,130.632 r270 top
R32 "1K" "R 0402_L" 131.877,130.632 r90 top
R33 "0R" "R 0402_L" 99.142,48.261 r90 top
R34 "1K" "R 0402_L" 144.12,130.632 r270 top
R35 "1K" "R 0402_L" 137.998,130.632 r270 top
R36 "0R" "R 0402_L" 110.245,66.95 r270 top
R37 "0R" "R 0402_L" 100.2,48.261 r90 top
R38 "75R" "R 0402_L" 204.32,124.637 r180 top
R39 "75R" "R 0402_L" 204.32,121.57 r180 top
R40 "75R" "R 0402_L" 204.32,118.503 r180 top
R41 "75R" "R 0402_L" 204.32,115.437 r180 top
R42 "75R" "R 0402_L" 204.32,112.37 r180 top
R43 "75R" "R 0402_L" 204.32,109.303 r180 top
R44 "0R" "R 1206_L" 213.85,130.478 r270 top
R45 "75R" "R 0402_L" 204.32,106.236 r180 top
R46 "75R" "R 0402_L" 204.32,103.169 r180 top
R47 "75R" "R 0402_L" 204.32,93.831 r180 top
R48 "75R" "R 0402_L" 204.32,90.766 r180 top
R49 "75R" "R 0402_L" 204.32,87.7 r180 top
R50 "75R" "R 0402_L" 204.32,84.635 r180 top
R51 "75R" "R 0402_L" 204.32,81.57 r180 top
R52 "75R" "R 0402_L" 204.32,78.504 r180 top
R53 "75R" "R 0402_L" 204.32,75.439 r180 top
R54 "75R" "R 0402_L" 204.32,72.373 r180 top
R55 "75R" "R 0402_L" 204.32,63.036 r180 top
R56 "75R" "R 0402_L" 204.32,59.956 r180 top
R57 "75R" "R 0402_L" 204.32,56.876 r180 top
R58 "75R" "R 0402_L" 204.32,53.796 r180 top
R59 "75R" "R 0402_L" 204.32,50.716 r180 top
R60 "75R" "R 0402_L" 204.32,47.636 r180 top
R61 "75R" "R 0402_L" 204.32,44.556 r180 top
R62 "75R" "R 0402_L" 204.32,41.476 r180 top
R63 "0R" "R 0402_L" 111.261,66.95 r270 top
R64 "0R" "R 0402_L" 112.882,69.461 r0 top
R65 "0R" "R 0402_L" 112.882,70.491 r0 top
R66 "0R" "R 0402_L" 111.898,71.864 r0 top
R67 "0R" "R 0402_L" 111.892,72.891 r0 top
R68 "0R" "R 0402_L" 122.775,72.568 r90 top
R69 "0R" "R 0402_L" 123.8,72.568 r90 top
R70 "0R" "R 0402_L" 125.775,67.933 r180 top
R71 "0R" "R 0402_L" 125.774,68.919 r180 top
R72 "0R" "R 0402_L" 122.723,62.84 r0 top
R73 "0R" "R 0402_L" 122.723,61.925 r0 top
RJ1 "RJ45X1" RJ45_网口不带灯X1 216.37,119.792 r90 top
RJ2 "RJ45X1" RJ45_网口不带灯X1 216.37,103.912 r90 top
RJ3 "RJ45_不带灯X4" RJ45_网口不带灯X4 215.695,66.567 r90 top
SW1 "6x6x5" "TSW DIP-4.5*4.5*3_V" 100.216,29.956 r0 top
SW2 "6x6x5" "TSW DIP-4.5*4.5*3_V" 93.179,29.956 r0 top
T1 "HN4824CG" TRANSFORMER/48P/SMD/GS5014LF 193.694,112.885 r270 top
T2 "HN4824CG" TRANSFORMER/48P/SMD/GS5014LF 193.694,82.07 r270 top
T3 "HN4824CG" TRANSFORMER/48P/SMD/GS5014LF 193.694,51.255 r270 top
TP1 "测试点" "TEST 1.6" 78.981,43.942 r90 top
TP2 "测试点" "TEST 1.6" 81.775,46.228 r90 top
TP3 "TP" "TEST 1" 98.944,46.716 r0 top
TP4 "测试点" "TEST 1.6" 169.723,48.362 r270 top
TP5 "TP" "TEST 1" 100.418,46.737 r0 top
TP6 "测试点" "TEST 1.6" 147.044,47.644 r270 top
TP7 "测试点" "TEST 1.6" 143.374,42.612 r0 top
TP8 "TP" "TEST 1" 95.502,64.852 r0 top
TP9 "TP" "TEST 1" 92.502,64.852 r0 top
TP10 "测试点" "TEST 1.6" 169.723,45.517 r0 top
TVS1 "tvs 5" TVS-6 116.508,114.364 r0 top
U1 "SY8156IADC" SOT23-6N 157.022,45.593 r270 top
U2 "HLK-RM20" HLK-RM20 115.836,54.083 r90 top locked
U3 "SIM卡座-翻盖式" NANOSIM 122.426,130.564 r270 top
U4 "SY8120IABC" SOT23-6N 147.829,37.96 r270 top
U5 "SY8113IABC" SOT23-6N 105.93,36.443 r270 top
U6 "" "MiniPCIE全卡 卡座" 92.225,71.9 r0 top locked
U7 "5G-Module" 5G_RM500Q-GL 92.225,54.225 r180 top locked

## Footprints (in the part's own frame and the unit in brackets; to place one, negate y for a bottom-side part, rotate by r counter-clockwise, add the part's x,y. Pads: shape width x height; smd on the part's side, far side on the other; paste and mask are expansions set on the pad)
5G_RM500Q-GL [mm] "M.2接口,RM500Q-GL,AINR10"
  round 6.2 hole 4.2: 0(0,-51.9)
  rect 0.3x1.55 smd: 1(-9.25,3.775) 2(-9,-3.775) 3(-8.75,3.775) 4(-8.5,-3.775) 5(-8.25,3.775) 6(-8,-3.775) 7(-7.75,3.775) 8(-7.5,-3.775) 9(-7.25,3.775) 10(-7,-3.775) 11(-6.75,3.775) 20(-4.5,-3.775) 21(-4.25,3.775) 22(-4,-3.775) 23(-3.75,3.775) 24(-3.5,-3.775) 25(-3.25,3.775) 26(-3,-3.775) 27(-2.75,3.775) 28(-2.5,-3.775) 29(-2.25,3.775) 30(-2,-3.775) 31(-1.75,3.775) 32(-1.5,-3.775) 33(-1.25,3.775) 34(-1,-3.775) 35(-0.75,3.775) 36(-0.5,-3.775) 37(-0.25,3.775) 38(0,-3.775) 39(0.25,3.775) 40(0.5,-3.775) 41(0.75,3.775) 42(1,-3.775) 43(1.25,3.775) 44(1.5,-3.775) 45(1.75,3.775) 46(2,-3.775) 47(2.25,3.775) 48(2.5,-3.775) 49(2.75,3.775) 50(3,-3.775) 51(3.25,3.775) 52(3.5,-3.775) 53(3.75,3.775) 54(4,-3.775) 55(4.25,3.775) 56(4.5,-3.775) 57(4.75,3.775) 58(5,-3.775) 59(5.25,3.775) 60(5.5,-3.775) 61(5.75,3.775) 62(6,-3.775) 63(6.25,3.775) 64(6.5,-3.775) 65(6.75,3.775) 66(7,-3.775) 67(7.25,3.775) 68(7.5,-3.775) 69(7.75,3.775) 70(8,-3.775) 71(8.25,3.775) 72(8.5,-3.775) 73(8.75,3.775) 74(9,-3.775) 75(9.25,3.775)
  rect 1.2x2.75 smd: 76(-10.35,3) 77(10.35,3)
  round 1.1 hole 1.1 unplated: ""(-10,-1.5)
  round 1.6 hole 1.6 unplated: ""(10,-1.5)
  silkscreen extent -15,-51.9 15,4.19
"C 0402_L" [mil]
  rect 20x20 smd: 1(-18,0) 2(18,0)
  silkscreen extent -36,-16 36,16, body extent -21,-10 18,10, height 21
"C 0603_L" [mm]
  rect 0.8x0.9 smd: 1(-0.7,0) 2(0.7,0)
  silkscreen extent -1.46,-0.64 1.45,0.65, body extent -0.83,-0.39 0.8,0.43, height 0.81
"C 0805_L" [mil] "无极性贴片电容"
  rect 35x50 smd: 1(-37.4,0) 2(37.4,0)
  silkscreen extent -67,-36 67,36, body extent -39,-24 39,24, height 20
"C 1206_L" [mil] "无极性贴片电容"
  rect 55x62 smd: 1(-55.12,0) 2(57.09,0)
  silkscreen extent -96,-44 98,44, body extent -63,-32 63,32, height 48
"C 1206_l" [mil] "无极性贴片电容"
  rect 55x62 smd: 1(-55.12,0) 2(57.09,0)
  silkscreen extent -96,-44 98,44, body extent -63,-32 63,32, height 48
"CT 6*6 - R" [mm] "直径6mm，高6mm"
  rect 2.7x1 smd: 1(3,0)
  oval 2.7x1 smd: 2(-3,0)
  silkscreen extent -3.3,-3.3 3.3,3.3, body extent -3.5,-3.15 3.5,3.15, height 6
"CT 8*12 - C" [mm] "直径8mm，高12mm"
  rect 3x1.3 smd: 1(4,0)
  oval 3x1.3 smd: 2(-4,0)
  silkscreen extent -4.2,-4.2 4.2,4.2, body extent -4.5,-4.15 4.5,4.15, height 12
DC-005 [mm] "5.5*2.1mm，DC30V,2.5A"
  rect 2x4 hole 0.8 slot 3 at 90 deg: 1(-6.2,0) 2(0,0)
  rect 4x2 hole 0.8 slot 2.5 at 0 deg: 3(-3.5,4.7)
  silkscreen extent -5.48,-4.5 7.5,4.5, body extent -6.55,-4.5 7.5,4.8, height 11.2
DFN-10 [mm] "DFN-10_B0524P"
  rect 0.2x0.7 smd: 1(-1,-0.45) 2(-0.5,-0.45) 4(0.5,-0.45) 5(1,-0.45) 6(1,0.45) 7(0.5,0.45) 9(-0.5,0.45) 10(-1,0.45)
  rect 0.4x0.7 smd: 3(0,-0.45) 8(0,0.45)
  silkscreen extent -1.44,-0.79 1.25,0.51
DO-214AC [mm]
  rect 2x1.8 smd: 1(0,0)
  rect 2x1.75 smd: 2(4.6,0)
  silkscreen extent -0.4,-1.35 5,1.35, body extent -0.2,-1.34 4.91,1.33, height 2.12
esd0402 [mm]
  rect 0.6x0.6 smd paste-100 mask+0.051: 1(-0.5,0) 2(0.5,0)
  silkscreen extent -1.18,-0.5 1.17,0.51
ESD0402#1 [mil]
  rect 20x20 smd: 1(-17.67,39.35) 2(18.33,39.35)
  silkscreen extent -43,20 43,60
ESD0402#2 [mil]
  rect 23.62x23.62 smd paste-3937.01 mask+2: 1(-19.69,0) 2(19.68,0)
  silkscreen extent -46,-20 46,20
"FU 0603" [mil] "贴片保险丝"
  rect 35x35 smd: 1(-35,0) 2(35,0)
  silkscreen extent -65,-25 65,25, body extent -31,-16 31,16, height 20
"FU 1206" [mil] "贴片保险丝"
  rect 50x65 smd: 1(-67.5,0) 2(67.5,0)
  silkscreen extent -105,-45 105,45, body extent -63,-32 63,32, height 34
HDR2.0-LI-9P [mm] "Connector; 2.0mm Header; 9 Position"
  rect 1.5x1.5 hole 0.711: 1(0,0)
  round 1.5 hole 0.711: 2(2,0) 3(4,0) 4(6,0) 5(8,0) 6(10,0)
  round 1.35 hole 0.8: 7(12,0) 8(14,0) 9(16,0)
  silkscreen extent -0.97,-0.99 17.02,0.99, body extent -0.97,-1 17,1, height 6
HDR2.54-LI-3P [mm] "排针，3脚"
  rect 1.7x1.7 hole 0.9: 1(-2.54,0)
  round 1.7 hole 0.9: 2(0,0) 3(2.54,0)
  silkscreen extent -3.81,-1.27 3.81,1.27, body extent -3.81,-1.27 3.81,1.27, height 8.5
HDR2.54-LI-6P [mm] "排针，6脚"
  rect 1.7x1.7 hole 0.9: 1(-6.35,0)
  round 1.7 hole 0.9: 2(-3.81,0) 3(-1.27,0) 4(1.27,0) 5(3.81,0) 6(6.35,0)
  silkscreen extent -7.62,-1.27 7.62,1.27, body extent -7.62,-1.27 7.62,1.27, height 8.5
HLK-RM20 [mm]
  round 6.2 hole 4.2: 0(0,-56) 0(0,0) 0(51,-56) 0(51,0)
  rect 0.5x2 smd paste+0 mask+0.051: A1(9.9,-51.55) A2(9.9,-55.95) A3(10.7,-51.55) A4(10.7,-55.95) A5(11.5,-51.55) A6(11.5,-55.95) A7(12.3,-51.55) A8(12.3,-55.95) A9(13.1,-51.55) A10(13.1,-55.95) A11(13.9,-51.55) A12(13.9,-55.95) A13(14.7,-51.55) A14(14.7,-55.95) A15(15.5,-51.55) A16(15.5,-55.95) A17(16.3,-51.55) A18(16.3,-55.95) A19(17.1,-51.55) A20(17.1,-55.95) A21(17.9,-51.55) A22(17.9,-55.95) A23(18.7,-51.55) A24(18.7,-55.95) A25(19.5,-51.55) A26(19.5,-55.95) A27(20.3,-51.55) A28(20.3,-55.95) A29(21.1,-51.55) A30(21.1,-55.95) A31(21.9,-51.55) A32(21.9,-55.95) A33(22.7,-51.55) A34(22.7,-55.95) A35(23.5,-51.55) A36(23.5,-55.95) A37(24.3,-51.55) A38(24.3,-55.95) A39(25.1,-51.55) A40(25.1,-55.95) A41(25.9,-51.55) A42(25.9,-55.95) A43(26.7,-51.55) A44(26.7,-55.95) A45(27.5,-51.55) A46(27.5,-55.95) A47(28.3,-51.55) A48(28.3,-55.95) A49(29.1,-51.55) A50(29.1,-55.95) A51(29.9,-51.55) A52(29.9,-55.95) A53(30.7,-51.55) A54(30.7,-55.95) A55(31.5,-51.55) A56(31.5,-55.95) A57(32.3,-51.55) A58(32.3,-55.95) A59(33.1,-51.55) A60(33.1,-55.95) A61(33.9,-51.55) A62(33.9,-55.95) A63(34.7,-51.55) A64(34.7,-55.95) A65(35.5,-51.55) A66(35.5,-55.95) A67(36.3,-51.55) A68(36.3,-55.95) A69(37.1,-51.55) A70(37.1,-55.95) A71(37.9,-51.55) A72(37.9,-55.95) A73(38.7,-51.55) A74(38.7,-55.95) A75(39.5,-51.55) A76(39.5,-55.95) A77(40.3,-51.55) A78(40.3,-55.95) A79(41.1,-51.55) A80(41.1,-55.95) B1(9.9,-0.05) B2(9.9,-4.45) B3(10.7,-0.05) B4(10.7,-4.45) B5(11.5,-0.05) B6(11.5,-4.45) B7(12.3,-0.05) B8(12.3,-4.45) B9(13.1,-0.05) B10(13.1,-4.45) B11(13.9,-0.05) B12(13.9,-4.45) B13(14.7,-0.05) B14(14.7,-4.45) B15(15.5,-0.05) B16(15.5,-4.45) B17(16.3,-0.05) B18(16.3,-4.45) B19(17.1,-0.05) B20(17.1,-4.45) B21(17.9,-0.05) B22(17.9,-4.45) B23(18.7,-0.05) B24(18.7,-4.45) B25(19.5,-0.05) B26(19.5,-4.45) B27(20.3,-0.05) B28(20.3,-4.45) B29(21.1,-0.05) B30(21.1,-4.45) B31(21.9,-0.05) B32(21.9,-4.45) B33(22.7,-0.05) B34(22.7,-4.45) B35(23.5,-0.05) B36(23.5,-4.45) B37(24.3,-0.05) B38(24.3,-4.45) B39(25.1,-0.05) B40(25.1,-4.45) B41(25.9,-0.05) B42(25.9,-4.45) B43(26.7,-0.05) B44(26.7,-4.45) B45(27.5,-0.05) B46(27.5,-4.45) B47(28.3,-0.05) B48(28.3,-4.45) B49(29.1,-0.05) B50(29.1,-4.45) B51(29.9,-0.05) B52(29.9,-4.45) B53(30.7,-0.05) B54(30.7,-4.45) B55(31.5,-0.05) B56(31.5,-4.45) B57(32.3,-0.05) B58(32.3,-4.45) B59(33.1,-0.05) B60(33.1,-4.45) B61(33.9,-0.05) B62(33.9,-4.45) B63(34.7,-0.05) B64(34.7,-4.45) B65(35.5,-0.05) B66(35.5,-4.45) B67(36.3,-0.05) B68(36.3,-4.45) B69(37.1,-0.05) B70(37.1,-4.45) B71(37.9,-0.05) B72(37.9,-4.45) B73(38.7,-0.05) B74(38.7,-4.45) B75(39.5,-0.05) B76(39.5,-4.45) B77(40.3,-0.05) B78(40.3,-4.45) B79(41.1,-0.05) B80(41.1,-4.45)
  round 0.9 hole 0.9 unplated: ""(7.4,-53.75) ""(7.4,-2.25)
  round 1.3 hole 1.3 unplated: ""(43.6,-53.75) ""(43.6,-2.25)
  silkscreen extent -3.5,-59.5 54.5,3.5
"L 4*4" [mm]
  rect 2x3 smd: 1(-1.651,0) 2(1.651,0)
  silkscreen extent -2.16,-2.03 2.16,2.03, body extent -2,-2 2,2, height 3.1
"L 5*5" [mm] "叠层电感"
  rect 1.9x2.5 smd: 1(2.431,0) 2(-2.431,0)
  silkscreen extent -2.78,-2.68 2.78,2.68, body extent -2.51,-2.47 2.49,2.53, height 4.1
"L 6*6" [mm] "叠层电感"
  rect 2.8x3.7 smd: 1(-3,0) 2(3,0)
  silkscreen extent -3.5,-3.3 3.5,3.3, body extent -3,-3 3,3, height 2.1
"L 0603" [mil] "小功率贴片电感"
  rect 35x35 smd: 1(-35,0) 2(35,0)
  silkscreen extent -65,-25 65,25, body extent -31,-16 31,16, height 31
"LED 3MM-G" [mm] "绿色3mm直插LED"
  rect 1.7x1.7 hole 0.9: 1(-1.27,0)
  round 1.7 hole 0.9: 2(1.27,0)
  silkscreen extent -2.01,-2 1.72,1.98, body extent -1.95,-1.95 1.64,1.95, height 5.55
"LED 3MM-R" [mm] "红色3mm直插LED"
  rect 1.7x1.7 hole 0.9: 1(-1.27,0)
  round 1.7 hole 0.9: 2(1.27,0)
  silkscreen extent -2.01,-2 1.72,1.98, body extent -1.95,-1.95 1.64,1.95, height 5.55
"LED 3MM-Y" [mm] "黄色3mm直插LED"
  rect 1.7x1.7 hole 0.9: 1(-1.27,0)
  round 1.7 hole 0.9: 2(1.27,0)
  silkscreen extent -2.01,-2 1.72,1.98, body extent -1.95,-1.95 1.64,1.95, height 5.55
"LED 0603B-L" [mil]
  rect 28x32 smd: 1(-25.67,-0.39) 2(25.51,-0.39)
  silkscreen extent -75,-25 52,25, body extent -31,-16 32,16, height 24
"M3 125X200" [mm] "M3螺丝孔，孔125Mil，焊盘200Mil"
  round 5.08 hole 3.175: 1(0,0)
"MiniPCIE全卡 卡座" [mm]
  rect 0.508x2 smd: 1(-11.8,-4.1) 2(-11.4,4.1) 3(-11,-4.1) 4(-10.6,4.1) 5(-10.2,-4.1) 6(-9.8,4.1) 7(-9.4,-4.1) 8(-9,4.1) 9(-8.6,-4.1) 10(-8.2,4.1) 11(-7.8,-4.1) 12(-7.4,4.1) 13(-7,-4.1) 14(-6.6,4.1) 15(-6.2,-4.1) 16(-5.8,4.1) 17(-2.2,-4.1) 18(-1.8,4.1) 19(-1.4,-4.1) 20(-1,4.1) 21(-0.6,-4.1) 22(-0.2,4.1) 23(0.2,-4.1) 24(0.6,4.1) 25(1,-4.1) 26(1.4,4.1) 27(1.8,-4.1) 28(2.2,4.1) 29(2.6,-4.1) 30(3,4.1) 31(3.4,-4.1) 32(3.8,4.1) 33(4.2,-4.1) 34(4.6,4.1) 35(5,-4.1) 36(5.4,4.1) 37(5.8,-4.1) 38(6.2,4.1) 39(6.6,-4.1) 40(7,4.1) 41(7.4,-4.1) 42(7.8,4.1) 43(8.2,-4.1) 44(8.6,4.1) 45(9,-4.1) 46(9.4,4.1) 47(9.8,-4.1) 48(10.2,4.1) 49(10.6,-4.1) 50(11,4.1) 51(11.4,-4.1) 52(11.8,4.1)
  round 1.6 hole 1.6 unplated: 53(-12.5,0) 67(-12.1,50.4)
  round 1.1 hole 1.1 unplated: 54(12.5,0) 68(12.1,50.4)
  rect 2.3x3.2 smd: 55(-14.65,-3.5) 56(14.65,-3.5)
  rect 4.8x3 smd: 63(-12.1,47.25) 64(12.1,47.25) 65(-12.1,53.55) 66(12.1,53.55)
  Keep-Out Layer pour cut-out: 13.304,0 13.304,0.053 13.283,0.21 13.202,0.405 13.073,0.573 12.905,0.702 12.71,0.783 12.553,0.804 12.5,0.804 12.5,0.804 12.447,0.804 12.29,0.783 12.095,0.702 11.927,0.573 11.798,0.405 11.717,0.21 11.696,0.053 11.696,0 11.696,0 11.696,-0.053 11.717,-0.21 11.798,-0.405 11.927,-0.573 12.095,-0.702 12.29,-0.783 12.447,-0.804 12.5,-0.804 12.5,-0.804 12.553,-0.804 12.71,-0.783 12.905,-0.702 13.073,-0.573 13.202,-0.405 13.283,-0.21 13.304,-0.053 13.304,0
  Keep-Out Layer pour cut-out: -11.446,0 -11.446,0.069 -11.473,0.275 -11.579,0.532 -11.748,0.752 -11.968,0.921 -12.225,1.027 -12.431,1.054 -12.5,1.054 -12.5,1.054 -12.569,1.054 -12.775,1.027 -13.032,0.921 -13.252,0.752 -13.421,0.532 -13.527,0.275 -13.554,0.069 -13.554,0 -13.554,0 -13.554,-0.069 -13.527,-0.275 -13.421,-0.532 -13.252,-0.752 -13.032,-0.921 -12.775,-1.027 -12.569,-1.054 -12.5,-1.054 -12.5,-1.054 -12.431,-1.054 -12.225,-1.027 -11.968,-0.921 -11.748,-0.752 -11.579,-0.532 -11.473,-0.275 -11.446,-0.069 -11.446,0
  Keep-Out Layer pour cut-out: 12.904,50.4 12.904,50.453 12.883,50.61 12.802,50.805 12.673,50.973 12.505,51.102 12.31,51.183 12.153,51.204 12.1,51.204 12.1,51.204 12.047,51.204 11.89,51.183 11.695,51.102 11.527,50.973 11.398,50.805 11.317,50.61 11.296,50.453 11.296,50.4 11.296,50.4 11.296,50.347 11.317,50.19 11.398,49.995 11.527,49.827 11.695,49.698 11.89,49.617 12.047,49.596 12.1,49.596 12.1,49.596 12.153,49.596 12.31,49.617 12.505,49.698 12.673,49.827 12.802,49.995 12.883,50.19 12.904,50.347 12.904,50.4
  Keep-Out Layer pour cut-out: -11.046,50.4 -11.046,50.469 -11.073,50.675 -11.179,50.932 -11.348,51.152 -11.568,51.321 -11.825,51.427 -12.031,51.454 -12.1,51.454 -12.1,51.454 -12.169,51.454 -12.375,51.427 -12.632,51.321 -12.852,51.152 -13.021,50.932 -13.127,50.675 -13.154,50.469 -13.154,50.4 -13.154,50.4 -13.154,50.331 -13.127,50.125 -13.021,49.868 -12.852,49.648 -12.632,49.479 -12.375,49.373 -12.169,49.346 -12.1,49.346 -12.1,49.346 -12.031,49.346 -11.825,49.373 -11.568,49.479 -11.348,49.648 -11.179,49.868 -11.073,50.125 -11.046,50.331 -11.046,50.4
  silkscreen extent -16,-6.16 16,56
NANOSIM [mm] "翻盖SIM卡座"
  rect 1.5x1.3 smd: 0(-1.836,1.02) 0(-1.786,-10.88) 0(6.914,1.02) 0(7.014,-10.88)
  rect 1.2x0.6 smd: 1(10.914,-3.03) 2(10.914,-5.58) 3(10.914,-8.08) 4(10.914,-6.83) 5(10.914,-4.33) 6(10.914,-1.78)
  silkscreen extent -2.74,-11.13 11.36,1.27
"R 0402_L" [mm] "1/16W贴片电阻"
  rect 0.5x0.5 smd: 1(-0.431,0.004) 2(0.469,0.004)
  silkscreen extent -0.8,-0.45 0.85,0.45, body extent -0.5,-0.25 0.5,0.25, height 0.3
"R 0402_l" [mm] "1/16W贴片电阻"
  rect 0.5x0.5 smd: 1(-0.431,0.004) 2(0.469,0.004)
  silkscreen extent -0.8,-0.45 0.85,0.45, body extent -0.5,-0.25 0.5,0.25, height 0.3
"R 1206_L" [mil] "1/4W贴片电阻"
  rect 55x62 smd: 1(-55.12,0) 2(57.09,0)
  silkscreen extent -96,-44 98,44, body extent -63,-31 63,32, height 22
RJ45_网口不带灯X1 [mm] "千兆网口"
  round 2.4 hole 1.7: 0(-7.94,-6.73) 0(7.94,-6.73)
  rect 1.524x1.524 hole 0.95: 1(-4.445,4.19)
  round 1.524 hole 0.95: 2(-3.175,6.73) 3(-1.905,4.19) 4(-0.635,6.73) 5(0.635,4.19) 6(1.905,6.73) 7(3.175,4.19) 8(4.445,6.73)
  round 3.3 hole 3.3 unplated: ""(-5.715,-2.16) ""(5.715,-2.16)
  silkscreen extent -7.94,-12.86 7.94,8.54
RJ45_网口不带灯X4 [mm] "千兆网口"
  round 1.5 hole 0.9: A1(-25.4,3.515) A2(-24.13,6.055) A3(-22.86,3.515) A4(-21.59,6.055) A5(-20.32,3.515) A6(-19.05,6.055) A7(-17.78,3.515) A8(-16.51,6.055) B1(-11.43,3.515) B2(-10.16,6.055) B3(-8.89,3.515) B4(-7.62,6.055) B5(-6.35,3.515) B6(-5.08,6.055) B7(-3.81,3.515) B8(-2.54,6.055) C1(2.54,3.515) C2(3.81,6.055) C3(5.08,3.515) C4(6.35,6.055) C5(7.62,3.515) C6(8.89,6.055) C7(10.16,3.515) C8(11.43,6.055) D1(16.51,3.515) D2(17.78,6.055) D3(19.05,3.515) D4(20.32,6.055) D5(21.59,3.515) D6(22.86,6.055) D7(24.13,3.515) D8(25.4,6.055)
  round 2.6 hole 1.6: EH(-29.405,-7.405) EH(-14,7.405) EH(0,7.405) EH(13.97,7.405) EH(29.405,-7.405)
  round 3.25 hole 3.25 unplated: ""(-26.67,-2.835) ""(26.67,-2.835)
  silkscreen extent -29.45,-13.64 29.45,7.51
SMA [mm]
  rect 2.5x1.778 smd: 1(-2.193,-0.006) 2(2.193,0.006)
  silkscreen extent -2.65,-1.52 2.45,1.53, body extent -2.74,-1.4 2.74,1.4, height 2.3
SMB [mm] "4.7*3.9*2.2mm(长宽高，不包括引脚）"
  rect 2.5x2.2 smd: 1(-2.35,0) 2(2.35,0)
  silkscreen extent -2.8,-1.9 3.57,1.9, body extent -2.63,-1.8 2.67,1.8, height 2.35
SMD_4P [mm] "共模电感"
  rect 0.75x0.4 smd: 1(-0.925,0.4) 2(-0.925,-0.4) 3(0.925,-0.4) 4(0.925,0.4)
  silkscreen extent -1,-0.85 1,0.85
SOT23-3N [mm] "3x1.3x1mm(长宽高)"
  rect 0.7x1.2 smd: 1(-0.95,-1.143) 2(0.95,-1.143) 3(0,1.143)
  silkscreen extent -1.72,-1.78 1.5,0.7, body extent -1.5,-1.2 1.5,1.2, height 1.05
SOT23-6N [mm] "3x1.6x1.1mm(长宽高)"
  rect 0.5x1.2 smd: 1(-0.95,-1.4) 2(0,-1.4) 3(0.95,-1.4) 4(0.95,1.4) 5(0,1.4) 6(-0.95,1.4)
  silkscreen extent -1.78,-1.78 1.55,0.51, body extent -1.5,-1.4 1.5,1.4, height 1.15
"TEST 1" [mm] "测试点1mm"
  round 1 smd paste-1: 1(0,0)
  silkscreen extent -0.61,-0.61 0.61,0.61
"TEST 1.6" [mm] "测试点1.6mm"
  round 1.6 smd paste-1.6: 1(0,0)
  silkscreen extent -1.02,-1.02 1.02,1.01
TRANSFORMER/48P/SMD/GS5014LF [mm] "千兆隔离变压器，贴片"
  rect 0.64x1.7 smd: 1(-11.73,-7.1) 2(-10.71,-7.1) 3(-9.69,-7.1) 4(-8.67,-7.1) 5(-7.65,-7.1) 6(-6.63,-7.1) 7(-5.61,-7.1) 8(-4.59,-7.1) 9(-3.57,-7.1) 10(-2.55,-7.1) 11(-1.53,-7.1) 12(-0.51,-7.1) 13(0.51,-7.1) 14(1.53,-7.1) 15(2.55,-7.1) 16(3.57,-7.1) 17(4.59,-7.1) 18(5.61,-7.1) 19(6.63,-7.1) 20(7.65,-7.1) 21(8.67,-7.1) 22(9.69,-7.1) 23(10.71,-7.1) 24(11.73,-7.1) 25(11.73,7.1) 26(10.71,7.1) 27(9.69,7.1) 28(8.67,7.1) 29(7.65,7.1) 30(6.63,7.1) 31(5.61,7.1) 32(4.59,7.1) 33(3.57,7.1) 34(2.55,7.1) 35(1.53,7.1) 36(0.51,7.1) 37(-0.51,7.1) 38(-1.53,7.1) 39(-2.55,7.1) 40(-3.57,7.1) 41(-4.59,7.1) 42(-5.61,7.1) 43(-6.63,7.1) 44(-7.65,7.1) 45(-8.67,7.1) 46(-9.69,7.1) 47(-10.71,7.1) 48(-11.73,7.1)
  silkscreen extent -14.69,-6.83 14,6.1
"TSW DIP-4.5*4.5*3_V" [mil] "三脚侧插"
  round 60 hole 31.5: 0(-0.01,-37.4) 1(-59.06,37.4) 2(59.05,37.4)
  silkscreen extent -89,-90 89,77
TVS-6 [mm] "SIM卡TVS管"
  rect 0.5x0.4 smd: 1(0,0) 2(0,-0.65) 3(0,-1.3) 4(1.9,-1.3) 5(1.9,-0.65) 6(1.9,0)
  silkscreen extent 0.38,-1.65 1.52,0.38
USB3.0-9P-DIP [mm]
  round 1.25 hole 0.75: 1(-3.5,0.25) 2(-1,0.25) 3(1,0.25) 4(3.5,0.25) 5(4,1.75) 6(2,1.75) 7(0,1.75) 8(-2,1.75) 9(-4,1.75)
  round 3 hole 2.3: 10(-6.57,-1.75) 11(6.57,-1.75)
  silkscreen extent -7.35,-13.53 7.35,3.07
XH2.54-LI-2P [mm] "接插件，2P"
  rect 1.7x1.7 hole 0.9: 1(-1.27,0)
  round 1.7 hole 0.9: 2(1.27,0)
  silkscreen extent -3.81,-3.51 3.74,2.37, body extent -3.77,-3.3 3.77,2.4, height 7.05

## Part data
C1 C5 C7 C10 C11 C12 C13 C15 C16 C17 C19 C22 C25 C27 C28: library part Cap, "Capacitor"
C2 C4 C6 C8 C14 C18 C20 C23 C24: library part Cap, "Capacitor", MANUFACTURER="Generic Components"
C3 C61 C62: library part "Cap Pol1", "Polarized Capacitor (Radial)"
C9 C21 C26 C30 C32 C33: library part CAP, "Capacitor"
C31 C63 C64 C65 C66: library part CAP1, "C?"
C34 C60: library part "CAP NP_Dup1", "Cap, HighVolt, SMD 1206, 2KV", MANUFACTURER=Arcotromics, Package=DIP, Package_Type=床杆
C35 C36 C37 C38 C39 C41 C42 C43 C44 C45 C46 C47 C48 C49 C50 C51 C52 C53 C54 C55 C56 C57 C58 C59: library part 0.1UF/25V_+80%-20%_CC_S0603, "Cap, MLCC, 0402, Y5V, 16V", MANUFACTURER=地穝, Package=SMD, Package_Type=Reel, Part Number=100-110-03400
C40: library part C, "无极性贴片电容"
C67 C68: library part C0402
CMK1 CMK2 CMK3: library part CMK1
D1 D3: library part Diode, "Default Diode", PackageDocument=Sep-1996
D2: library part TVS
D4 D5 D6 D8 D9 D10 D11 D13 D14 D19 D20: library part LED0, "贴片发光二极管"
D7 D12 D15 D17 D18: library part "Diode BAS70", "Silicon AF Schottky Diode for High-Speed Switching", PackageDocument=Sep-2001
F1 F2: library part "Fuse 1", "Fuse"
FB1: library part INDUCTOR, MFR_Name=MURATA, MFR_PN=BLM15PX121SZ1D
J1: "Low Voltage Power Supply Connector"
J5 J6 J7 J8: "铜柱孔"
JP1 JP7: library part "Header 3", "3P接插件"
JP2 JP3 JP4 JP6 JP8: library part "Header 6", "6P接插件"
JP5: library part "Header 2", "2P接插件"
JP9 JP10: library part "Header 9", "9P接插件"
L1 L2 L4: library part LineInductors
Q1: library part 8050-SMD, "高频放大-NPN型"
R1 R2 R4 R5 R6 R7 R9 R10 R12 R13 R17 R20 R23 R26 R31 R32 R34 R35 R44 R68 R69 R70 R71 R72 R73: library part R, "贴片电阻"
R3 R15 R18 R21 R22 R24 R25 R28 R36 R63: library part Res2, "Resistor"
R8: "Resistor"
R11 R14: library part RES1, "R?"
R16 R19 R29 R30 R33 R37 R64 R65 R66 R67: library part RES2
R27: library part Res1, "Resistor"
R38 R39 R40 R41 R42 R43 R45 R46: library part R75_1%_S0603, "Resistor, 0402, 5%", MANUFACTURER=驾м, Package=SMD, Package_Type=Reel, Part Number=110-110-03300
R47 R48 R49 R50 R51 R52 R53 R54 R55 R56 R57 R58 R59 R60 R61 R62: library part R75_1%_S0603, "Resistor, SMD 0402, 5%", MANUFACTURER=驾м, Package=SMD, Package_Type=Reel, Part Number=110-110-03300
RJ1 RJ2: library part RJ45X1_4, MANUFACTURER=救┹, Manufacturer's Part Number=PJ-A1-BXBH-FDNNN-1, Part Number=214411*12311105
RJ3: BOM_Manufacturer=CONNFLY, BOM_Manufacturer Part=DS1129-02-S80BP
SW1 SW2: library part "TSW DIP-6x6", "直插6x6轻触开关"
T1 T2 T3: library part "XMER 2P G2PM109N"
TP1 TP2 TP4 TP6 TP7 TP10: library part TP
TVS1: library part Tvs
U1: library part SY8105
U3: library part SIM座
U4: library part SY8201
U5: "VIN=4.5-18V  I=3A"
U6: library part Component_1

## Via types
v1: diameter 0.5, hole 0.3, Top Layer to Bottom Layer, tented both sides, 747 vias

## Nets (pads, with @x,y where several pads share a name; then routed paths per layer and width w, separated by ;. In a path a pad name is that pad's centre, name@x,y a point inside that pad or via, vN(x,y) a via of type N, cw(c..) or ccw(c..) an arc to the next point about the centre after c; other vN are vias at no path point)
4GUSB_D1_N: R63.1 U6.36 | length 23.1
  Top Layer w0.283: U6.36@97.625,76.553 97.625,76.746 97.807,76.928 97.807,77.474 99.261,78.928 101.623,78.928 101.731,79.037 v1(101.79,79.037) ; v1(111.084,67.996) 111.084,67.937 111.157,67.864 111.157,67.489 R63.1@111.265,67.38
  Bottom Layer w0.283: v1(101.79,79.037) 101.849,79.037 101.957,78.928 105.152,78.928 107.496,76.584 107.496,72.189 111.064,68.621 111.064,68.015 v1(111.084,67.996)
4GUSB_D1_P: R36.1 U6.38 | length 21.5
  Top Layer w0.283: U6.38@98.425,76.373 98.425,76.746 98.243,76.928 98.243,77.294 99.442,78.493 v1@101.623,78.493 ; R36.1@110.249,67.38 110.358,67.489 110.358,67.864 110.431,67.937 v1(110.431,67.996)
  Bottom Layer w0.283: v1(101.79,78.384) 101.849,78.384 101.957,78.493 104.971,78.493 107.061,76.403 107.061,72.008 110.431,68.638 v1(110.431,67.996)
4GUSB_D_N: R18.1 R33.2 R63.2 U7.9 | length 25.5
  Top Layer w0.283: R33.2@99.138,48.73 99.247,48.838 99.284,48.838 99.507,49.062 99.507,49.793 99.475,49.825 99.475,51.075 99.507,51.107 v1@99.507,51.7 ; R63.2@111.265,66.48 111.157,66.372 111.141,66.372 110.975,66.206 110.975,65.7 111.235,65.44 111.549,65.44 v1@111.584,65.476 ; v1(111.779,65.517) 111.82,65.559 112.346,65.559 R18.1@112.447,65.66
  Bottom Layer w0.283: v1(99.399,51.867) 99.399,51.926 99.507,52.034 99.507,55.626 109.29,65.409 v1@111.612,65.409
4GUSB_D_P: R15.1 R36.2 R37.2 U7.7 | length 25.5
  Top Layer w0.283: v1@99.943,51.7 99.943,51.107 99.975,51.075 99.975,49.825 99.943,49.793 99.943,48.983 R37.2@100.196,48.73 ; R36.2@110.249,66.48 110.358,66.372 110.374,66.372 110.54,66.206 110.54,65.52 111.055,65.005 111.522,65.005 111.554,64.973 v1@111.612,64.973 ; v1(111.779,64.865) 111.838,64.865 111.883,64.82 112.338,64.82 R15.1@112.447,64.711
  Bottom Layer w0.283: v1(100.051,51.867) 100.051,51.926 99.943,52.034 99.943,55.446 109.47,64.973 v1@111.612,64.973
